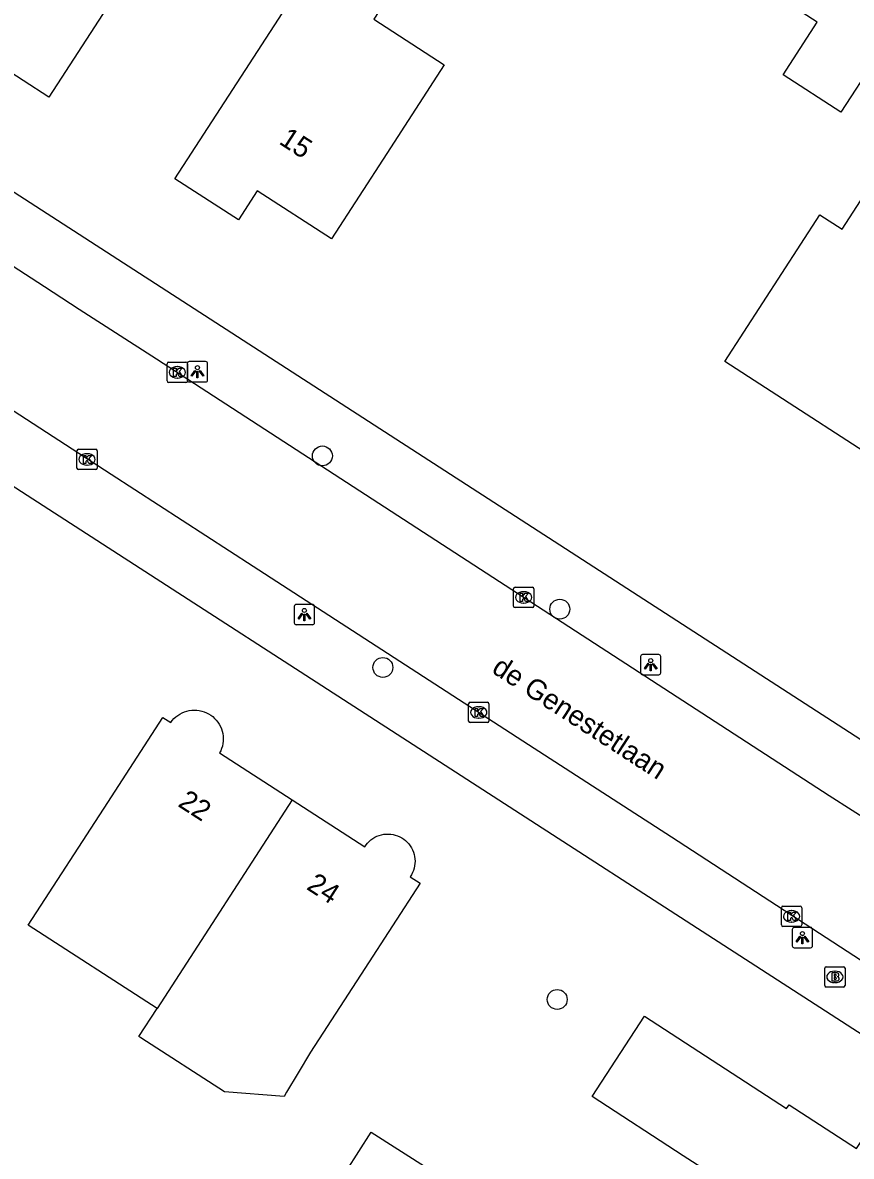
# Model space of a CAD drawing. Extents: x 161141 to 161601, y 381708 to 382245.
# Drawn here: x 161419 to 161459.7, y 381968.7 to 382024.5 of the extents above; entities that cross this region are included whole.
import ezdxf

# ---------------------------------------------------------------- set-up
doc = ezdxf.new("R2010")
doc.units = 0
for name, color, linetype in [('IMGEO_Boom', 7, 'Continuous'), ('IMGEO_Brandkraan', 7, 'Continuous'), ('IMGEO_Kolk', 7, 'Continuous'), ('IMGEO_Lichtpunt', 7, 'Continuous'), ('IMGEO_Openbare_ruimte_label', 7, 'Continuous'), ('IMGEO_Pand', 7, 'Continuous'), ('IMGEO_Pand_nummerreeks', 7, 'Continuous'), ('IMGEO_Rijbaan_lokaal_open', 7, 'Continuous'), ('IMGEO_Voetpad_open', 7, 'Continuous')]:
    doc.layers.add(name, color=color, linetype=linetype)

msp = doc.modelspace()

# ---------------------------------------------------------------- linework, layer by layer
at = {"layer": 'IMGEO_Boom'}
for centre in [(161433.712, 382003.149), (161445.391, 381995.605), (161436.687, 381992.736), (161445.263, 381976.392)]:
    msp.add_circle(centre, 0.489, dxfattribs=at)
at = {"layer": 'IMGEO_Brandkraan'}
for p, q in [((161458.42, 381977.078), (161458.42, 381977.93)), ((161458.495, 381978.004), (161459.347, 381978.004)), ((161459.421, 381977.93), (161459.421, 381977.078)), ((161458.908, 381977.784), (161458.933, 381977.784)), ((161459.347, 381977.004), (161458.495, 381977.004)), ((161458.931, 381977.224), (161458.906, 381977.224))]:
    msp.add_line(p, q, dxfattribs=at)
for points in [[(161458.42, 381977.078), (161458.42, 381977.93)], [(161458.495, 381978.004), (161459.347, 381978.004)], [(161459.421, 381977.93), (161459.421, 381977.078)], [(161458.768, 381977.704), (161458.768, 381977.304), (161458.981, 381977.304)], [(161458.999, 381977.704), (161458.768, 381977.704)], [(161458.947, 381977.623), (161458.893, 381977.623), (161458.893, 381977.547)], [(161458.893, 381977.547), (161458.946, 381977.547)], [(161458.955, 381977.471), (161458.893, 381977.471), (161458.893, 381977.39)], [(161458.893, 381977.39), (161458.955, 381977.39)], [(161459.347, 381977.004), (161458.495, 381977.004)]]:
    msp.add_lwpolyline(points, dxfattribs=at)
for centre, radius, start, end in [((161458.497, 381977.928), 0.0765, 91.552, 178.448), ((161458.497, 381977.928), 0.0765, 91.552, 178.448), ((161459.345, 381977.928), 0.0765, 1.552, 88.448), ((161459.345, 381977.928), 0.0765, 1.552, 88.448), ((161458.948, 381977.585), 0.0379, 267.8285, 90.9355), ((161458.956, 381977.43), 0.0404, 269.8759, 90.5077), ((161458.987, 381977.555), 0.251, 268.6676, 293.5347), ((161459.003, 381977.559), 0.145, 59.4692, 91.5367), ((161459.028, 381977.606), 0.0922, 285.5137, 58.1501), ((161459.033, 381977.414), 0.105, 301.3115, 78.989), ((161458.497, 381977.08), 0.0765, 181.552, 268.448), ((161458.497, 381977.08), 0.0765, 181.552, 268.448), ((161459.345, 381977.08), 0.0765, 271.552, 358.448), ((161459.345, 381977.08), 0.0765, 271.552, 358.448)]:
    msp.add_arc(centre, radius, start, end, dxfattribs=at)
for centre, major_axis, ratio, start_param, end_param in [((161458.907, 381977.504), (-0.387, 0.002), 0.722429, 4.712389, 7.853982), ((161458.932, 381977.504), (-0.39, 0.002), 0.717154, 1.570796, 4.712389)]:
    msp.add_ellipse(centre, major_axis=major_axis, ratio=ratio, start_param=start_param, end_param=end_param, dxfattribs=at)
at = {"layer": 'IMGEO_Kolk'}
for p, q in [((161426.074, 382006.837), (161426.074, 382007.689)), ((161426.149, 382007.763), (161427.001, 382007.763)), ((161426.562, 382007.543), (161426.587, 382007.543)), ((161427.075, 382007.689), (161427.075, 382006.837)), ((161426.585, 382006.983), (161426.56, 382006.983)), ((161427.001, 382006.763), (161426.149, 382006.763)), ((161421.709, 382003.476), (161422.561, 382003.476)), ((161421.634, 382002.55), (161421.634, 382003.402)), ((161422.122, 382003.256), (161422.147, 382003.256)), ((161422.635, 382003.402), (161422.635, 382002.55)), ((161422.561, 382002.476), (161421.709, 382002.476)), ((161422.145, 382002.696), (161422.12, 382002.696)), ((161443.113, 381995.759), (161443.113, 381996.611)), ((161443.188, 381996.685), (161444.04, 381996.685)), ((161443.601, 381996.465), (161443.626, 381996.465)), ((161444.114, 381996.611), (161444.114, 381995.759)), ((161444.04, 381995.685), (161443.188, 381995.685)), ((161443.624, 381995.905), (161443.599, 381995.905)), ((161440.905, 381990.095), (161440.905, 381990.947)), ((161440.98, 381991.021), (161441.832, 381991.021)), ((161441.393, 381990.801), (161441.418, 381990.801)), ((161441.906, 381990.947), (161441.906, 381990.095)), ((161441.416, 381990.241), (161441.391, 381990.241)), ((161441.832, 381990.021), (161440.98, 381990.021)), ((161456.29, 381980.059), (161456.29, 381980.911)), ((161456.365, 381980.985), (161457.217, 381980.985)), ((161456.778, 381980.765), (161456.803, 381980.765)), ((161457.291, 381980.911), (161457.291, 381980.059)), ((161456.801, 381980.205), (161456.776, 381980.205)), ((161457.217, 381979.985), (161456.365, 381979.985))]:
    msp.add_line(p, q, dxfattribs=at)
for points in [[(161426.074, 382006.837), (161426.074, 382007.689)], [(161426.149, 382007.763), (161427.001, 382007.763)], [(161426.395, 382007.463), (161426.518, 382007.463), (161426.518, 382007.312), (161426.648, 382007.463), (161426.812, 382007.463), (161426.666, 382007.312), (161426.819, 382007.063), (161426.667, 382007.063), (161426.582, 382007.227), (161426.518, 382007.16), (161426.518, 382007.063), (161426.395, 382007.063), (161426.395, 382007.463)], [(161427.075, 382007.689), (161427.075, 382006.837)], [(161427.001, 382006.763), (161426.149, 382006.763)], [(161421.709, 382003.476), (161422.561, 382003.476)], [(161421.634, 382002.55), (161421.634, 382003.402)], [(161421.955, 382003.176), (161422.078, 382003.176), (161422.078, 382003.025), (161422.208, 382003.176), (161422.372, 382003.176), (161422.226, 382003.025), (161422.379, 382002.776), (161422.227, 382002.776), (161422.142, 382002.94), (161422.078, 382002.873), (161422.078, 382002.776), (161421.955, 382002.776), (161421.955, 382003.176)], [(161422.635, 382003.402), (161422.635, 382002.55)], [(161422.561, 382002.476), (161421.709, 382002.476)], [(161443.113, 381995.759), (161443.113, 381996.611)], [(161443.188, 381996.685), (161444.04, 381996.685)], [(161443.434, 381996.385), (161443.557, 381996.385), (161443.557, 381996.234), (161443.687, 381996.385), (161443.851, 381996.385), (161443.705, 381996.234), (161443.858, 381995.985), (161443.706, 381995.985), (161443.621, 381996.149), (161443.557, 381996.082), (161443.557, 381995.985), (161443.434, 381995.985), (161443.434, 381996.385)], [(161444.114, 381996.611), (161444.114, 381995.759)], [(161444.04, 381995.685), (161443.188, 381995.685)], [(161440.905, 381990.095), (161440.905, 381990.947)], [(161440.98, 381991.021), (161441.832, 381991.021)], [(161441.226, 381990.721), (161441.349, 381990.721), (161441.349, 381990.57), (161441.479, 381990.721), (161441.643, 381990.721), (161441.497, 381990.57), (161441.65, 381990.321), (161441.498, 381990.321), (161441.413, 381990.485), (161441.349, 381990.418), (161441.349, 381990.321), (161441.226, 381990.321), (161441.226, 381990.721)], [(161441.906, 381990.947), (161441.906, 381990.095)], [(161441.832, 381990.021), (161440.98, 381990.021)], [(161456.29, 381980.059), (161456.29, 381980.911)], [(161456.365, 381980.985), (161457.217, 381980.985)], [(161456.611, 381980.685), (161456.734, 381980.685), (161456.734, 381980.534), (161456.864, 381980.685), (161457.028, 381980.685), (161456.882, 381980.534), (161457.035, 381980.285), (161456.883, 381980.285), (161456.798, 381980.449), (161456.734, 381980.382), (161456.734, 381980.285), (161456.611, 381980.285), (161456.611, 381980.685)], [(161457.291, 381980.911), (161457.291, 381980.059)], [(161457.217, 381979.985), (161456.365, 381979.985)]]:
    msp.add_lwpolyline(points, dxfattribs=at)
for centre, start, end in [((161426.151, 382007.687), 91.552, 178.448), ((161426.151, 382007.687), 91.552, 178.448), ((161426.999, 382007.687), 1.552, 88.448), ((161426.999, 382007.687), 1.552, 88.448), ((161426.151, 382006.839), 181.552, 268.448), ((161426.151, 382006.839), 181.552, 268.448), ((161426.999, 382006.839), 271.552, 358.448), ((161426.999, 382006.839), 271.552, 358.448), ((161421.711, 382003.4), 91.552, 178.448), ((161421.711, 382003.4), 91.552, 178.448), ((161422.559, 382003.4), 1.552, 88.448), ((161422.559, 382003.4), 1.552, 88.448), ((161421.711, 382002.552), 181.552, 268.448), ((161421.711, 382002.552), 181.552, 268.448), ((161422.559, 382002.552), 271.552, 358.448), ((161422.559, 382002.552), 271.552, 358.448), ((161443.19, 381996.609), 91.552, 178.448), ((161443.19, 381996.609), 91.552, 178.448), ((161444.038, 381996.609), 1.552, 88.448), ((161444.038, 381996.609), 1.552, 88.448), ((161443.19, 381995.761), 181.552, 268.448), ((161443.19, 381995.761), 181.552, 268.448), ((161444.038, 381995.761), 271.552, 358.448), ((161444.038, 381995.761), 271.552, 358.448), ((161440.982, 381990.945), 91.552, 178.448), ((161440.982, 381990.945), 91.552, 178.448), ((161441.83, 381990.945), 1.552, 88.448), ((161441.83, 381990.945), 1.552, 88.448), ((161440.982, 381990.097), 181.552, 268.448), ((161440.982, 381990.097), 181.552, 268.448), ((161441.83, 381990.097), 271.552, 358.448), ((161441.83, 381990.097), 271.552, 358.448), ((161456.367, 381980.909), 91.552, 178.448), ((161456.367, 381980.909), 91.552, 178.448), ((161457.215, 381980.909), 1.552, 88.448), ((161457.215, 381980.909), 1.552, 88.448), ((161456.367, 381980.061), 181.552, 268.448), ((161456.367, 381980.061), 181.552, 268.448), ((161457.215, 381980.061), 271.552, 358.448), ((161457.215, 381980.061), 271.552, 358.448)]:
    msp.add_arc(centre, 0.0765, start, end, dxfattribs=at)
for centre, major_axis, ratio, start_param, end_param in [((161426.561, 382007.263), (-0.387, 0.002), 0.722429, 4.712389, 7.853982), ((161426.586, 382007.263), (-0.39, 0.002), 0.717154, 1.570796, 4.712389), ((161422.121, 382002.976), (-0.387, 0.002), 0.722429, 4.712389, 7.853982), ((161422.146, 382002.976), (-0.39, 0.002), 0.717154, 1.570796, 4.712389), ((161443.6, 381996.185), (-0.387, 0.002), 0.722429, 4.712389, 7.853982), ((161443.625, 381996.185), (-0.39, 0.002), 0.717154, 1.570796, 4.712389), ((161441.392, 381990.521), (-0.387, 0.002), 0.722429, 4.712389, 7.853982), ((161441.417, 381990.521), (-0.39, 0.002), 0.717154, 1.570796, 4.712389), ((161456.777, 381980.485), (-0.387, 0.002), 0.722429, 4.712389, 7.853982), ((161456.802, 381980.485), (-0.39, 0.002), 0.717154, 1.570796, 4.712389)]:
    msp.add_ellipse(centre, major_axis=major_axis, ratio=ratio, start_param=start_param, end_param=end_param, dxfattribs=at)
at = {"layer": 'IMGEO_Lichtpunt'}
for p, q in [((161427.067, 382007.694), (161427.067, 382006.887)), ((161427.067, 382007.694), (161427.067, 382006.887)), ((161427.969, 382007.789), (161427.161, 382007.789)), ((161427.969, 382007.789), (161427.161, 382007.789)), ((161428.063, 382006.887), (161428.063, 382007.694)), ((161428.063, 382006.887), (161428.063, 382007.694)), ((161427.161, 382006.793), (161427.969, 382006.793)), ((161427.161, 382006.793), (161427.969, 382006.793)), ((161432.327, 381995.743), (161432.327, 381994.936)), ((161432.327, 381995.743), (161432.327, 381994.936)), ((161433.229, 381995.838), (161432.421, 381995.838)), ((161433.229, 381995.838), (161432.421, 381995.838)), ((161433.323, 381994.936), (161433.323, 381995.743)), ((161433.323, 381994.936), (161433.323, 381995.743)), ((161432.421, 381994.842), (161433.229, 381994.842)), ((161432.421, 381994.842), (161433.229, 381994.842)), ((161449.363, 381993.275), (161449.363, 381992.468)), ((161449.363, 381993.275), (161449.363, 381992.468)), ((161450.265, 381993.37), (161449.457, 381993.37)), ((161450.265, 381993.37), (161449.457, 381993.37)), ((161450.359, 381992.468), (161450.359, 381993.275)), ((161450.359, 381992.468), (161450.359, 381993.275)), ((161449.457, 381992.374), (161450.265, 381992.374)), ((161449.457, 381992.374), (161450.265, 381992.374)), ((161456.827, 381979.84), (161456.827, 381979.033)), ((161456.827, 381979.84), (161456.827, 381979.033)), ((161457.729, 381979.935), (161456.921, 381979.935)), ((161457.729, 381979.935), (161456.921, 381979.935)), ((161457.823, 381979.033), (161457.823, 381979.84)), ((161457.823, 381979.033), (161457.823, 381979.84)), ((161456.921, 381978.939), (161457.729, 381978.939)), ((161456.921, 381978.939), (161457.729, 381978.939))]:
    msp.add_line(p, q, dxfattribs=at)
for points in [[(161427.441, 382007.358), (161427.48, 382007.33), (161427.292, 382007.068), (161427.254, 382007.095), (161427.441, 382007.358)], [(161427.543, 382007.31), (161427.59, 382007.31), (161427.59, 382006.988), (161427.543, 382006.988), (161427.543, 382007.31)], [(161427.653, 382007.33), (161427.691, 382007.357), (161427.878, 382007.095), (161427.839, 382007.067), (161427.653, 382007.33)], [(161432.701, 381995.407), (161432.74, 381995.379), (161432.552, 381995.117), (161432.514, 381995.144), (161432.701, 381995.407)], [(161432.803, 381995.359), (161432.85, 381995.359), (161432.85, 381995.037), (161432.803, 381995.037), (161432.803, 381995.359)], [(161432.913, 381995.379), (161432.951, 381995.406), (161433.138, 381995.144), (161433.099, 381995.116), (161432.913, 381995.379)], [(161449.737, 381992.939), (161449.776, 381992.911), (161449.588, 381992.649), (161449.55, 381992.676), (161449.737, 381992.939)], [(161449.839, 381992.891), (161449.886, 381992.891), (161449.886, 381992.569), (161449.839, 381992.569), (161449.839, 381992.891)], [(161449.949, 381992.911), (161449.987, 381992.938), (161450.174, 381992.676), (161450.135, 381992.648), (161449.949, 381992.911)], [(161457.201, 381979.504), (161457.24, 381979.476), (161457.052, 381979.214), (161457.014, 381979.241), (161457.201, 381979.504)], [(161457.413, 381979.476), (161457.451, 381979.503), (161457.638, 381979.241), (161457.599, 381979.213), (161457.413, 381979.476)], [(161457.303, 381979.456), (161457.35, 381979.456), (161457.35, 381979.134), (161457.303, 381979.134), (161457.303, 381979.456)]]:
    msp.add_lwpolyline(points, dxfattribs=at)
for centre in [(161427.566, 382007.492), (161432.826, 381995.541), (161449.862, 381993.073), (161457.326, 381979.638)]:
    msp.add_circle(centre, 0.0994, dxfattribs=at)
for centre, start, end in [((161427.161, 382007.694), 90, 180), ((161427.161, 382007.694), 90, 180), ((161427.969, 382007.694), 0, 90), ((161427.969, 382007.694), 0, 90), ((161427.161, 382006.887), 180, 270), ((161427.161, 382006.887), 180, 270), ((161427.969, 382006.887), 270, 0), ((161427.969, 382006.887), 270, 360), ((161432.421, 381995.743), 90, 180), ((161432.421, 381995.743), 90, 180), ((161433.229, 381995.743), 0, 90), ((161433.229, 381995.743), 0, 90), ((161432.421, 381994.936), 180, 270), ((161432.421, 381994.936), 180, 270), ((161433.229, 381994.936), 270, 0), ((161433.229, 381994.936), 270, 360), ((161449.457, 381993.275), 90, 180), ((161449.457, 381993.275), 90, 180), ((161450.265, 381993.275), 0, 90), ((161450.265, 381993.275), 0, 90), ((161449.457, 381992.468), 180, 270), ((161449.457, 381992.468), 180, 270), ((161450.265, 381992.468), 270, 0), ((161450.265, 381992.468), 270, 360), ((161456.921, 381979.84), 90, 180), ((161456.921, 381979.84), 90, 180), ((161457.729, 381979.84), 0, 90), ((161457.729, 381979.84), 0, 90), ((161456.921, 381979.033), 180, 270), ((161456.921, 381979.033), 180, 270), ((161457.729, 381979.033), 270, 0), ((161457.729, 381979.033), 270, 360)]:
    msp.add_arc(centre, 0.0946, start, end, dxfattribs=at)
at = {"layer": 'IMGEO_Pand'}
for points in [[(161460.898, 382022.668), (161459.22, 382020.074), (161456.379, 382021.912), (161458.057, 382024.506), (161451.086, 382029.016), (161453.802, 382033.215), (161455.991, 382036.598), (161466.421, 382029.851)], [(161434.04, 382034.173), (161437.118, 382032.18), (161435.549, 382029.755), (161438.371, 382027.928), (161436.248, 382024.648), (161439.71, 382022.407), (161436.878, 382018.034), (161434.16, 382013.837), (161430.507, 382016.202), (161429.579, 382014.769), (161426.46, 382016.788), (161432.983, 382026.86), (161430.388, 382028.546)], [(161430.388, 382028.546), (161426.785, 382030.887), (161420.257, 382020.807), (161413.923, 382024.909)], [(161463.237, 382001.496), (161453.51, 382007.789), (161458.187, 382015.018), (161459.285, 382014.308), (161462.86, 382019.835)], [(161425.579, 381975.942), (161419.245, 381980.042), (161423.153, 381986.083), (161425.87, 381990.279), (161426.251, 381990.027), (161426.326, 381990.125), (161426.409, 381990.217), (161426.499, 381990.3), (161426.597, 381990.376), (161426.7, 381990.443), (161426.809, 381990.501), (161426.923, 381990.549), (161427.041, 381990.586), (161427.161, 381990.614), (161427.283, 381990.631), (161427.406, 381990.637), (161427.53, 381990.633), (161427.652, 381990.618), (161427.773, 381990.592), (161427.891, 381990.556), (161428.005, 381990.509), (161428.115, 381990.453), (161428.22, 381990.388), (161428.318, 381990.314), (161428.41, 381990.231), (161428.494, 381990.141), (161428.571, 381990.044), (161428.638, 381989.941), (161428.696, 381989.832), (161428.744, 381989.718), (161428.783, 381989.601), (161428.811, 381989.481), (161428.829, 381989.359), (161428.835, 381989.236), (161428.832, 381989.112), (161428.817, 381988.99), (161428.792, 381988.869), (161428.756, 381988.751), (161428.71, 381988.636), (161428.655, 381988.526), (161432.225, 381986.214)], [(161432.225, 381986.214), (161435.793, 381983.903), (161435.858, 381983.999), (161435.931, 381984.088), (161436.011, 381984.171), (161436.099, 381984.247), (161436.192, 381984.314), (161436.291, 381984.374), (161436.395, 381984.425), (161436.503, 381984.466), (161436.614, 381984.499), (161436.727, 381984.521), (161436.842, 381984.534), (161436.957, 381984.536), (161437.073, 381984.529), (161437.187, 381984.512), (161437.299, 381984.485), (161437.409, 381984.448), (161437.515, 381984.402), (161437.616, 381984.348), (161437.713, 381984.284), (161437.804, 381984.213), (161437.888, 381984.133), (161437.965, 381984.047), (161438.034, 381983.955), (161438.095, 381983.857), (161438.148, 381983.754), (161438.191, 381983.647), (161438.225, 381983.536), (161438.249, 381983.424), (161438.264, 381983.309), (161438.268, 381983.194), (161438.263, 381983.078), (161438.247, 381982.964), (161438.222, 381982.851), (161438.187, 381982.741), (161438.143, 381982.634), (161438.09, 381982.532), (161438.028, 381982.434), (161438.517, 381982.114), (161435.799, 381977.918), (161433.134, 381973.801), (161432.523, 381972.782), (161431.953, 381971.83), (161431.825, 381971.616), (161428.895, 381971.844), (161424.776, 381974.511), (161424.687, 381974.566), (161425.579, 381975.942)], [(161432.225, 381986.214), (161425.579, 381975.942)], [(161449.552, 381975.564), (161456.544, 381971.017), (161456.666, 381971.205), (161459.982, 381969.048), (161460.425, 381969.728), (161463.898, 381967.469), (161463.48, 381966.826), (161467.104, 381964.469), (161462.709, 381957.712), (161458.518, 381960.439), (161452.348, 381964.452), (161454.026, 381967.032), (161451.457, 381968.703), (161446.982, 381971.614), (161449.552, 381975.564)], [(161436.113, 381969.868), (161453.299, 381958.899), (161451.149, 381955.529), (161454.905, 381953.132), (161454.472, 381952.454), (161457.1, 381950.777), (161455.205, 381947.808), (161455.632, 381947.535), (161453.984, 381944.959), (161453.554, 381945.234), (161453.216, 381944.706), (161445.564, 381949.575), (161445.725, 381949.828), (161440.611, 381953.092), (161443.837, 381958.147), (161436.391, 381962.9), (161436.43, 381962.961), (161433.072, 381965.105), (161436.113, 381969.868)]]:
    msp.add_lwpolyline(points, dxfattribs=at)
at = {"layer": 'IMGEO_Rijbaan_lokaal_open'}
for points in [[(161311.536, 382081.664), (161356.674, 382052.498), (161362.411, 382048.813), (161375.585, 382040.285), (161382.572, 382035.748), (161395.928, 382027.083), (161402.927, 382022.535), (161416.852, 382013.552), (161420.042, 382011.494), (161421.741, 382010.379), (161425.551, 382007.922), (161458.647, 381986.439), (161460.91, 381984.988)], [(161480.897, 381964.849), (161471.977, 381970.646), (161450.889, 381984.377), (161443.856, 381988.93), (161430.314, 381997.713), (161423.318, 382002.239), (161408.287, 382012.005), (161402.555, 382015.697), (161398.439, 382018.395), (161388.068, 382025.069), (161381.679, 382029.228), (161366.307, 382039.161), (161359.944, 382043.32), (161345.442, 382052.667), (161339.032, 382056.795), (161328.504, 382063.628), (161325.321, 382065.668), (161306.338, 382077.878)]]:
    msp.add_lwpolyline(points, dxfattribs=at)
at = {"layer": 'IMGEO_Voetpad_open'}
for points in [[(161313.623, 382083.997), (161443.483, 382000), (161462.38, 381987.777)], [(161474.804, 381965.241), (161421.048, 382000), (161306.066, 382074.349)]]:
    msp.add_lwpolyline(points, dxfattribs=at)

# ---------------------------------------------------------------- texts
at = {"layer": 'IMGEO_Openbare_ruimte_label'}
msp.add_text('de Genestetlaan', height=1, rotation=327.041, dxfattribs=at).set_placement((161441.986, 381992.521))
at = {"layer": 'IMGEO_Pand_nummerreeks'}
for s, rotation, p in [('15', 327.0805, (161431.526, 382018.544)), ('22', 327.1523, (161426.557, 381985.932)), ('24', 327.1523, (161432.882, 381981.848))]:
    msp.add_text(s, height=1, rotation=rotation, dxfattribs=at).set_placement(p)

doc.saveas('drawing.dxf')
